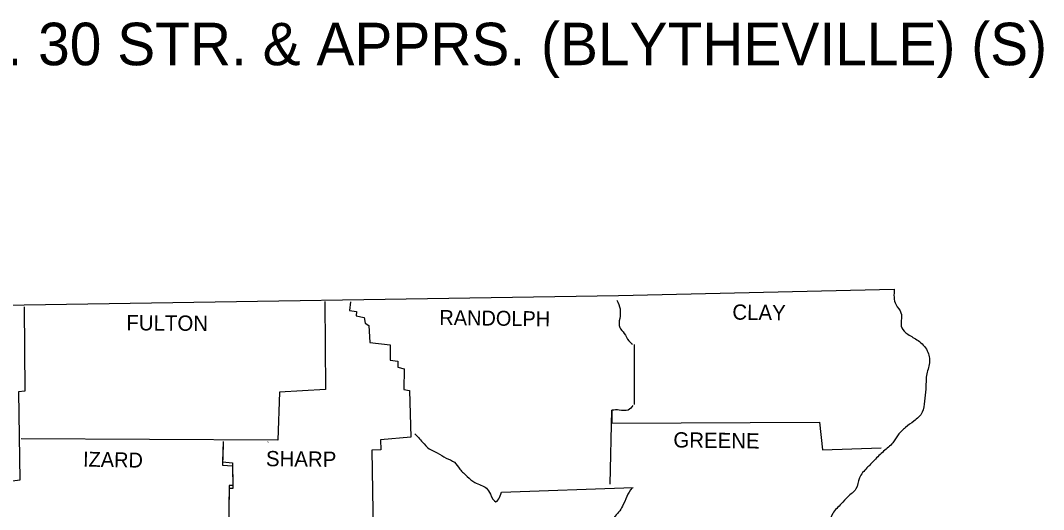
# Model space of a CAD drawing. Extents: x 191 to 3403, y 68 to 2102.
# Drawn here: x 2999.8 to 3281.6, y 1900.2 to 2035 of the extents above; entities that cross this region are included whole.
import ezdxf

# ---------------------------------------------------------------- set-up
doc = ezdxf.new("R2010")
doc.units = 0
for name, color, linetype in [('1', 7, 'Continuous'), ('2', 7, 'Continuous'), ('R_Border', 7, 'Continuous')]:
    doc.layers.add(name, color=color, linetype=linetype)

msp = doc.modelspace()

# ---------------------------------------------------------------- linework, layer by layer
at = {"layer": '1'}
for points in [[(2703.71, 1956.42), (2861.92, 1956.32), (3000.75, 1956.61), (3164.54, 1959.16), (3240.46, 1960.92)], [(3000.75, 1956.03), (3000.95, 1932.74), (2999.28, 1932.64), (2999.58, 1908.28), (2992.73, 1907.3), (2993.32, 1900.75), (2995.66, 1897.71), (2995.47, 1889.98), (2982.16, 1889.5), (2981.67, 1877.56), (2969.54, 1877.17), (2968.95, 1862.69), (2969.64, 1861.51), (2969.93, 1838.42), (2990.87, 1837.05), (2990.58, 1785.49), (3007.21, 1785), (3007.21, 1732.56), (2994.1, 1731.58), (2993.12, 1720.04), (2971.11, 1719.94)], [(3083.62, 1957.49), (3083.82, 1933.23), (3071.1, 1932.55), (3070.71, 1919.24), (2999.97, 1919.63)], [(3090.67, 1957.4), (3090.37, 1955.05), (3092.33, 1954.76), (3092.23, 1953.58), (3094.48, 1953.09), (3094.68, 1951.53), (3095.75, 1950.84), (3096.05, 1946.15), (3101.63, 1945.56), (3101.63, 1941.35), (3103.68, 1941.06), (3103.68, 1939.39), (3105.44, 1938.9), (3105.34, 1933.23), (3106.91, 1932.94), (3107.3, 1920.12), (3098.98, 1919.34), (3099.08, 1916.6), (3096.54, 1916.5), (3097.42, 1866.01), (3136.85, 1865.13), (3137.53, 1786.66), (3111.8, 1785.98), (3111.31, 1799.19)], [(3168.84, 1945.66), (3168.84, 1929.12)], [(3162.19, 1907.11), (3162.68, 1927.56), (3162.68, 1923.94), (3219.91, 1924.23), (3220.7, 1916.6), (3236.84, 1917.18)], [(3055.64, 1918.95), (3055.44, 1913.27), (3058.18, 1913.07), (3058.28, 1906.81), (3057.3, 1906.81), (3056.91, 1882.16), (3054.66, 1881.18), (3054.66, 1872.96)], [(3055.64, 1918.06), (3055.44, 1912.39), (3058.18, 1912.19), (3058.28, 1905.93), (3057.3, 1905.93), (3056.91, 1881.28), (3054.66, 1880.3), (3054.66, 1872.08)], [(3067.87, 1918.75), (3067.97, 1918.85)], [(3132.25, 1904.95), (3168.55, 1906.23)]]:
    msp.add_lwpolyline(points, dxfattribs=at)
for points in [[(3240.46, 1960.92), (3240.95, 1956.61), (3242.32, 1954.36), (3242.52, 1950.25), (3244.18, 1948.49), (3247.02, 1946.73), (3249.56, 1943.89), (3250.15, 1940.57), (3249.36, 1937.14), (3249.17, 1933.33), (3248.78, 1930), (3248.19, 1926.97), (3245.84, 1924.52), (3243.59, 1922.76), (3241.54, 1920.71), (3240.07, 1918.55), (3237.53, 1916.21), (3234.98, 1913.76), (3232.93, 1911.61), (3230.87, 1908.87), (3229.89, 1905.83), (3227.64, 1903.68), (3225.88, 1901.73), (3223.53, 1899.08), (3222.36, 1896.44), (3220.11, 1893.41), (3219.62, 1890.47), (3218.15, 1888.13), (3218.06, 1887.73)], [(3164.05, 1957.89), (3164.93, 1955.44), (3164.83, 1952.8), (3164.83, 1950.35), (3166.1, 1948.69), (3167.37, 1946.63), (3168.35, 1945.75)], [(3168.45, 1928.83), (3167.18, 1927.56), (3164.73, 1927.56), (3162.68, 1927.56)], [(3108.38, 1921), (3110.53, 1918.75), (3112.39, 1916.89), (3114.54, 1915.81), (3117.08, 1914.35), (3119.33, 1913.17), (3120.8, 1911.31), (3122.86, 1909.26), (3124.91, 1907.6), (3128.14, 1906.03), (3129.22, 1904.37), (3130.68, 1902.31), (3132.25, 1904.95)], [(3168.25, 1906.13), (3166.79, 1903.78), (3165.61, 1901.04), (3163.26, 1897.91), (3161.5, 1894.88), (3161.21, 1892.82), (3159.84, 1890.08), (3159.06, 1887.34), (3158.18, 1884.99), (3158.18, 1882.55), (3158.86, 1880.1), (3158.67, 1877.85), (3157.2, 1876.78), (3156.81, 1873.94), (3156.22, 1871.98), (3154.95, 1870.03), (3153.09, 1868.56), (3151.13, 1866.31), (3149.67, 1865.33)]]:
    msp.add_spline(points, degree=3, dxfattribs=at)

# ---------------------------------------------------------------- texts
at = {"layer": '2'}
for s, height, rotation, p in [('CLAY', 4.206, 359.2258, (3195.85, 1952.5)), ('FULTON', 4.206, 359.4996, (3028.93, 1949.57)), ('RANDOLPH', 4.109, 359.2583, (3115.13, 1951.04)), ('GREENE', 4.207, 359.2361, (3179.6, 1917.28)), ('SHARP', 4.206, 359.3905, (3067.38, 1912.1)), ('IZARD', 4.108, 358.9258, (3016.99, 1912))]:
    msp.add_text(s, height=height, rotation=rotation, dxfattribs=at).set_placement(p)
at = {"layer": 'R_Border'}
msp.add_text('DITCH NO. 30 STR. & APPRS. (BLYTHEVILLE) (S)', height=11.724, dxfattribs=at).set_placement((2920.15, 2022.61))

doc.saveas('drawing.dxf')
